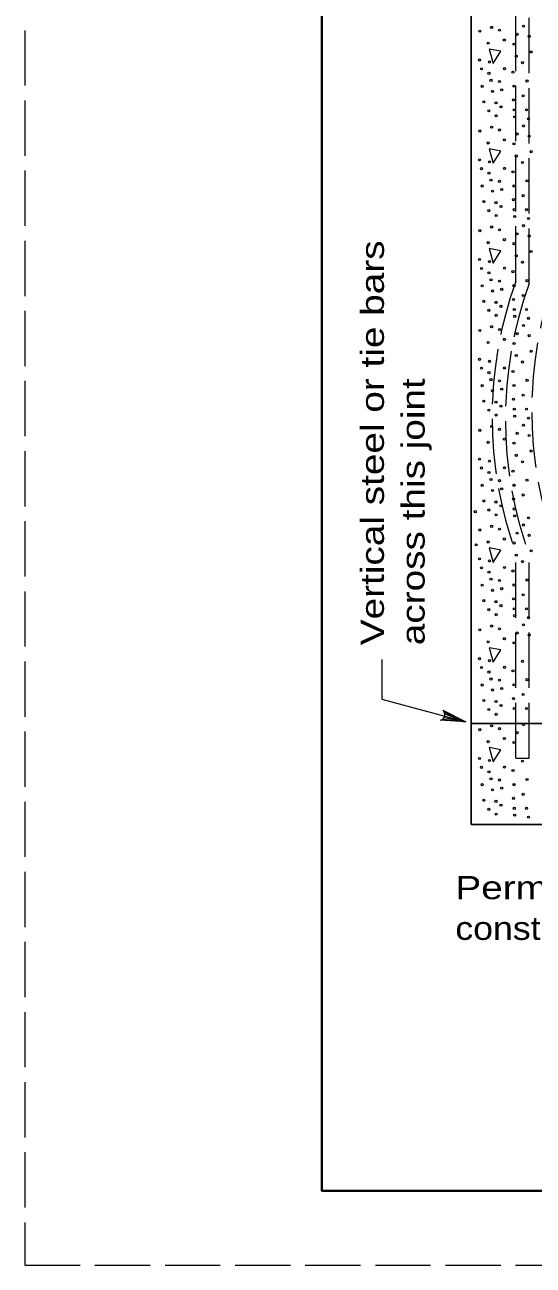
# Model space of a CAD drawing. Extents: x 1329.9 to 1363.9, y 715.5 to 737.5.
# Drawn here: x 1329.86 to 1333.29, y 715.5 to 723.85 of the extents above; entities that cross this region are included whole.
import ezdxf

# ---------------------------------------------------------------- set-up
doc = ezdxf.new("R2010")
doc.units = 0
doc.header["$LTSCALE"] = 0.062
doc.linetypes.add('LONG_DASHED', pattern=[7.5, 6, -1.5])
doc.layers.add('1', color=7, linetype='Continuous', lineweight=13)

msp = doc.modelspace()

# ---------------------------------------------------------------- linework, layer by layer
at = {"layer": '1', "linetype": 'LONG_DASHED'}
for p, q in [((1333.259, 722.105), (1333.259, 728.643)), ((1333.16925, 722.11933), (1333.16925, 724.87933)), ((1333.16925, 718.91142), (1333.16925, 720.28942)), ((1333.259, 718.91142), (1333.259, 720.27508)), ((1333.16925, 718.91142), (1333.259, 718.91142))]:
    msp.add_line(p, q, dxfattribs=at)
at = {"layer": '1', "lineweight": 25}
for p, q in [((1332.86792, 718.46475), (1332.86792, 724.27833)), ((1332.86792, 719.143), (1338.4845, 719.143)), ((1332.86792, 718.46475), (1338.4845, 718.46475))]:
    msp.add_line(p, q, dxfattribs=at)
at = {"layer": '1'}
for p, q in [((1332.26725, 719.5745), (1332.26725, 719.30867)), ((1332.26725, 719.30867), (1332.83167, 719.15592)), ((1332.67883, 719.17392), (1332.83167, 719.15592)), ((1332.68642, 719.18342), (1332.83167, 719.15592)), ((1332.68817, 719.2205), (1332.83167, 719.15592)), ((1332.69067, 719.19408), (1332.83167, 719.15592)), ((1332.69142, 719.20875), (1332.83167, 719.15592))]:
    msp.add_line(p, q, dxfattribs=at)
at = {"layer": '1', "linetype": 'LONG_DASHED'}
msp.add_lwpolyline([(1329.86333, 715.4975), (1363.86333, 715.4975), (1363.86333, 737.4975), (1329.86333, 737.4975)], close=True, dxfattribs=at)
at = {"layer": '1', "lineweight": 25}
msp.add_lwpolyline([(1363.36333, 715.9975), (1331.86333, 715.9975), (1331.86333, 736.9975)], dxfattribs=at)
at = {"layer": '1', "lineweight": 40}
msp.add_lwpolyline([(1331.86333, 736.9975), (1363.36333, 736.9975), (1363.36333, 715.9975), (1331.86333, 715.9975)], close=True, dxfattribs=at)
msp.add_lwpolyline([(1331.86333, 736.9975), (1363.36333, 736.9975), (1363.36333, 715.9975), (1331.86333, 715.9975)], close=True, dxfattribs=at)
at = {"layer": '1'}
for points in [[(1332.99042, 723.68392), (1333.01608, 723.58667), (1333.06825, 723.66883)], [(1332.99042, 723.01233), (1333.01608, 722.915), (1333.06825, 722.99717)], [(1332.99042, 722.34067), (1333.01608, 722.24333), (1333.06825, 722.3255)], [(1332.99042, 720.32575), (1333.01608, 720.22833), (1333.06825, 720.3105)], [(1332.99042, 719.65408), (1333.01608, 719.55675), (1333.06825, 719.63892)], [(1332.99042, 718.9825), (1333.01608, 718.88517), (1333.06825, 718.96725)]]:
    msp.add_lwpolyline(points, close=True, dxfattribs=at)
msp.add_lwpolyline([(1332.677, 719.2345), (1332.83167, 719.15592), (1332.66033, 719.1655)], dxfattribs=at)
for centre in [(1333.00592, 723.8296), (1333.22114, 723.83805), (1332.92709, 723.80425), (1333.05815, 723.81057), (1333.09151, 723.74436), (1333.17805, 723.78337), (1333.25883, 723.76915), (1332.98276, 723.72348), (1333.15664, 723.71716), (1333.27141, 723.6646), (1332.92371, 723.61014), (1332.99132, 723.59654), (1333.17208, 723.63555), (1333.21321, 723.59201), (1332.9374, 723.55031), (1332.98789, 723.52036), (1333.09325, 723.5521), (1333.14977, 723.52854), (1332.94163, 723.43333), (1333.00163, 723.47324), (1333.05899, 723.46501), (1333.07353, 723.40977), (1333.15664, 723.43417), (1333.24429, 723.46842), (1332.95421, 723.32878), (1333.01184, 723.39885), (1333.03505, 723.32178), (1333.15352, 723.34143), (1333.21855, 723.36863), (1332.98762, 723.26799), (1333.06872, 723.2952), (1333.15865, 723.27432), (1333.24091, 723.27432), (1333.00592, 723.15796), (1333.03589, 723.23503), (1333.16118, 723.22809), (1333.22114, 723.16641), (1333.2546, 723.21449), (1332.92709, 723.1326), (1333.05815, 723.13893), (1333.09151, 723.07271), (1333.17805, 723.11172), (1333.25883, 723.09751), (1332.98276, 723.05184), (1333.15664, 723.04551), (1333.27141, 722.99296), (1332.92371, 722.9385), (1332.99132, 722.9249), (1333.17208, 722.96391), (1333.21321, 722.92036), (1332.9374, 722.87866), (1332.98789, 722.84872), (1333.09325, 722.88045), (1333.14977, 722.85689), (1332.94163, 722.76169), (1333.00163, 722.80159), (1333.05899, 722.79336), (1333.07353, 722.73812), (1333.15664, 722.76252), (1333.24429, 722.79678), (1332.95421, 722.65713), (1333.01184, 722.72721), (1333.15352, 722.66978), (1333.21855, 722.69698), (1332.98762, 722.59635), (1333.03505, 722.65014), (1333.06872, 722.62355), (1333.15865, 722.60267), (1333.24091, 722.60267), (1333.00592, 722.48631), (1333.03589, 722.56338), (1333.16118, 722.55644), (1333.22114, 722.49476), (1333.2546, 722.54284), (1332.92709, 722.46096), (1333.05815, 722.46728), (1333.17805, 722.44008), (1333.25883, 722.42586), (1332.98276, 722.38019), (1333.09151, 722.40107), (1333.15664, 722.37387), (1333.27141, 722.32131), (1332.92371, 722.26685), (1332.99132, 722.25325), (1333.17208, 722.29226), (1333.21321, 722.24872), (1332.9374, 722.20702), (1332.98789, 722.17707), (1333.09325, 722.20881), (1333.14977, 722.18525), (1332.94163, 722.09004), (1333.00163, 722.12995), (1333.05899, 722.12172), (1333.15664, 722.09088), (1333.24429, 722.12513), (1332.95421, 721.98549), (1333.01184, 722.05556), (1333.07353, 722.06648), (1333.15352, 721.99814), (1333.21855, 722.02534), (1332.98762, 721.9247), (1333.03505, 721.97849), (1333.06872, 721.9519), (1333.15865, 721.93103), (1333.24091, 721.93103), (1333.03589, 721.89174), (1333.16118, 721.8848), (1333.22114, 721.82312), (1333.2546, 721.8712), (1332.92709, 721.78931), (1333.00592, 721.81466), (1333.05815, 721.79563), (1333.17805, 721.76843), (1333.25883, 721.75422), (1332.98276, 721.70854), (1333.09151, 721.72942), (1333.15664, 721.70222), (1332.92371, 721.5952), (1332.99132, 721.5816), (1333.17208, 721.62062), (1333.21321, 721.57707), (1333.27141, 721.64966), (1332.9374, 721.53537), (1332.98789, 721.50543), (1333.09325, 721.53716), (1333.14977, 721.5136), (1332.94163, 721.41839), (1333.00163, 721.4583), (1333.05899, 721.45007), (1333.15664, 721.41923), (1333.24429, 721.45349), (1333.01184, 721.38392), (1333.07353, 721.39483), (1333.15352, 721.32649), (1333.21855, 721.35369), (1332.95421, 721.31384), (1332.98762, 721.25306), (1333.03505, 721.30684), (1333.06872, 721.28026), (1333.15865, 721.25938), (1333.24091, 721.25938), (1333.03589, 721.22009), (1333.16118, 721.21315), (1333.22114, 721.15147), (1333.2546, 721.19955), (1332.92709, 721.11766), (1333.00592, 721.14302), (1333.05815, 721.12399), (1333.17805, 721.09679), (1333.25883, 721.08257), (1332.98276, 721.0369), (1333.09151, 721.05778), (1333.15664, 721.03057), (1332.92371, 720.92356), (1332.99132, 720.90996), (1333.17208, 720.94897), (1333.21321, 720.90542), (1333.27141, 720.97802), (1332.9374, 720.86373), (1332.98789, 720.83378), (1333.09325, 720.86552), (1333.14977, 720.84195), (1332.94163, 720.74675), (1333.00163, 720.78666), (1333.05899, 720.77843), (1333.15664, 720.74759), (1333.24429, 720.78184), (1333.01184, 720.71227), (1333.07353, 720.72318), (1333.15352, 720.65484), (1333.21855, 720.68205), (1332.89601, 720.5696), (1332.95421, 720.6422), (1332.98762, 720.58141), (1333.03505, 720.6352), (1333.06872, 720.60861), (1333.15865, 720.58774), (1333.03589, 720.54845), (1333.16118, 720.5415), (1333.2546, 720.5279), (1332.92709, 720.44602), (1333.00592, 720.47137), (1333.05815, 720.45234), (1333.17805, 720.42514), (1333.22114, 720.47983), (1333.25883, 720.41093), (1332.90135, 720.34622), (1332.98276, 720.36525), (1333.09151, 720.38613), (1333.15664, 720.35893), (1332.92371, 720.25191), (1332.99132, 720.23831), (1333.17208, 720.27732), (1333.21321, 720.23378), (1333.27141, 720.30637), (1332.9374, 720.19208), (1332.98789, 720.16214), (1333.09325, 720.19387), (1333.14977, 720.17031), (1332.94163, 720.0751), (1333.00163, 720.11501), (1333.05899, 720.10678), (1333.15664, 720.07594), (1333.24429, 720.1102), (1333.01184, 720.04062), (1333.07353, 720.05154), (1333.15352, 719.9832), (1333.21855, 720.0104), (1332.95421, 719.97055), (1332.98762, 719.90977), (1333.03505, 719.96355), (1333.06872, 719.93697), (1333.15865, 719.91609), (1333.24091, 719.91609), (1333.03589, 719.8768), (1333.16118, 719.86986), (1333.2546, 719.85626), (1332.92709, 719.77437), (1333.00592, 719.79973), (1333.05815, 719.7807), (1333.17805, 719.7535), (1333.22114, 719.80818), (1333.25883, 719.73928), (1332.98276, 719.69361), (1333.09151, 719.71449), (1333.15664, 719.68728), (1332.92371, 719.58027), (1332.99132, 719.56667), (1332.9374, 719.52044), (1332.98789, 719.49049), (1333.09325, 719.52223), (1333.14977, 719.49866), (1333.21321, 719.56213), (1332.94163, 719.40346), (1333.00163, 719.44336), (1333.05899, 719.43514), (1333.15664, 719.4043), (1333.24429, 719.43855), (1333.01184, 719.36898), (1333.07353, 719.37989), (1333.21855, 719.33876), (1332.95421, 719.2989), (1332.98762, 719.23812), (1333.03505, 719.29191), (1333.06872, 719.26532), (1333.15352, 719.31155), (1333.15865, 719.24445), (1333.24091, 719.24445), (1333.03589, 719.20515), (1332.92709, 719.10273), (1333.00592, 719.12808), (1333.05815, 719.10905), (1333.17805, 719.08185), (1333.22114, 719.13653), (1332.98276, 719.02196), (1333.09151, 719.04284), (1333.15664, 719.01564), (1332.92371, 718.90862), (1332.9374, 718.84879), (1332.98789, 718.81885), (1332.99132, 718.89502), (1333.09325, 718.85058), (1333.14977, 718.82702), (1333.21321, 718.89049), (1332.94163, 718.73181), (1333.00163, 718.77172), (1333.05899, 718.76349), (1333.15664, 718.73265), (1333.24429, 718.76691), (1333.01184, 718.69733), (1333.07353, 718.70825), (1333.21855, 718.66711), (1332.95421, 718.62726), (1332.98762, 718.56647), (1333.03505, 718.62026), (1333.06872, 718.59368), (1333.15352, 718.63991), (1333.15865, 718.5728), (1333.24091, 718.5728), (1333.03589, 718.53351), (1333.16118, 718.52657), (1333.2546, 718.51297)]:
    msp.add_ellipse(centre, major_axis=(0, 0.00718), ratio=0.944544, dxfattribs=at)
at = {"layer": '1', "linetype": 'LONG_DASHED'}
for centre in [(1335.66941, 721.24918), (1335.40227, 721.20573), (1335.49199, 721.1914)]:
    msp.add_ellipse(centre, major_axis=(0, -2.53448), ratio=0.944544, start_param=4.343612, end_param=5.0823137, dxfattribs=at)
at = {"layer": '1'}
msp.add_ellipse((1332.65543, 719.2036), major_axis=(0, -0.03844), ratio=0.944544, start_param=0.1352095, end_param=2.5058226, dxfattribs=at)

# ---------------------------------------------------------------- texts
at = {"layer": '1', "width": 1.25}
for s, p in [('Vertical steel or tie bars', (1332.28083, 719.671)), ('across this joint', (1332.55492, 719.671))]:
    msp.add_text(s, height=0.156, rotation=90, dxfattribs=at).set_placement(p)
at = {"layer": '1'}
for s, width, p in [('Permissible', 1.25, (1332.76183, 717.96133)), ('const. joint', 1.15, (1332.76183, 717.68725))]:
    msp.add_text(s, height=0.156, dxfattribs=dict(at, width=width)).set_placement(p)

doc.saveas('drawing.dxf')
